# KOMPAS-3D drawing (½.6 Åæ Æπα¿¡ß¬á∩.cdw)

Views: Вид 1
Referenced files in C:\Program Files\ASCON\KOMPAS-3D V10\Sys\: SPDS.lcs, Graphic.lcs
Referenced files in \\F-server\проектирование\Проекты\РЗА и ПА Тюменские РС\4. Проект\ЭП\Туринская\Рабочая документация\: план располодения оборудования на ПС.cdw
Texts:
  Текст на чертеже
  Размерные надписи
  Шероховатость
  Линия-выноска #1
  Линия-выноска #2
  Линия-выноска #3
  Отклонения формы и база
  Заголовок таблицы
  Ячейка таблицы
  Стрелка вида
  Обозначение изменения
  Фигурная скобка
  Номер узла
  Марка координационной оси
  VRCB
  Выносная надпись
  Обозначение узла
  Марка/позиционное обозначение с линией-выноской
  Марка/позиционное обозначение на линии
  Марка/позиционное обозначение без линии-выноски
  Лит-Масса-Масштаб
  Материал-Предприятие
  Title Specification
  Body Specification ( left align )
  Body Specificaton ( centered )
  Без имени
  Normal
  heading 1
  Знак Знак Знак Знак Знак Знак
  Verdana
  Body Text
  MS Sans Serif
  Txt
  Simplex
  TXT
  Обычный
  Термин
  Список определений
  Адрес
  Цитаты
  Форматированный
  Courier New
  Z-конец формы
  Z-начало формы
  Additional DXF text style 0
  Абзац Знак
  Body Text 3
  Title
  ТекстШаг1
  Шрифт 2.5
  Заголовки
  txt
  heading 2
  AGOpus
  footer
  Денис
  RUSTXT
  Обычный (веб)
  ООббыыччнныыйй
  Definition Term
  Definition List
  Address
  Blockquote
  Preformatted
  z-Bottom of Form
  z-Top of Form
  header
  NormalParagraphStyle
  ссылки
  Подпись в квадратике
  табл
  цепи
  Маркировка
  клеммы, контакты
  тексты табл
  Тексты. 3,2
  ЗОНА_привяз
  текст переноса
  ТТееррммиинн
  ССппииссоокк ооппррееддееллеенниийй
  ААддрреесс
  ЦЦииттааттыы
  ФФооррммааттиирроовваанннныыйй
  Z-ккооннеецц ффооррммыы
  Z-ннааччааллоо ффооррммыы
  GOST 2.304 type A
  rustxt
  heading 8
  heading 3
  heading 6
  heading 7
  russ
  heading 4
  heading 5
  heading 9
  HeliosLight
  Pa3
  Pa1
  Три с половиной
  style2
  Table Contents
  Table Heading
  ГОСТ_МНЕ
  ESK - Обозначение
  маркировка
  ISOCP
  ROMANS
  SIMPLEX
  Текст 3,5
  Tahoma
  CNBNDG+TimesNewRoman
  Subtitle
  FR5
  romanc
  eskd1
  Pa15
  Pa18
  Аппараты
  подписи
  Состав чартежа
  ячейка табл.
  Ссылки
  Пояснения
  Клеммник текст
  CM12
  romans
  gif
  Пояснения 2
  текст табл
  ISOCPEUR
  CC С?т?и?л?ь? П?о? ц?е?н?т?р?у?
  Normal (Web)
  ошиновка
  Топосъемка
  лотки
  Демонтаж
  Монтаж
  Номер
  на плане
  Постоянные здания и сооружения
  ОПУ
  Существующее
  КРУН 10 кВ
  Трансформатор 1Т, маслоприемник
  Существующий
  Трансформатор 2Т, маслоприемник
  Временные здания и сооружения
  III
  Вагон-дом для кратковременного отдых рабочих
  Уборная
  Дизельная электростанция
  Контейнеры для ТБО (0,75м 3 )и жидких хоз.-быт.стоков(1м 3 )
  «Екатерина» 9,0х3,0
  Туалетная кабина "Люкс"
  ОАО ПКТИпромстрой
  АДС 45-Т400 РЯ
  Экспликация зданий и сооружений
  Примечания:
  1. Для нужд строительства (размещение задействованного в строительстве персонала, обеспечение электроэнергией)
  использовать временные мобильные инвентарные здания;
  2. При выполнении всех строительно-монтажных работ на площадке необходимо руководствоваться требованиями
  СНиП 12-03-2001 "Безопасность труда в строительстве. Общие требования", СНиП 12-04-2002 "Безопасность труда в
  строительстве. Строительное производство", а также ПОТ-РМ-016-2001/РД 153-34.0-03.150-00 "Межотраслевые правила по
  охране труда (правила безопасности) при эксплуатации электроустановок";
  3. Наружное освещение строительной площадки осуществляется за счет существующего освещения;
  4. Под временные сооружения (поз. II, III и IV) устраивается площадка из дорожных плит ПД 60-20 на щебеночном основании
  толщиной 15см;
  5. На период строительства для электроснабжения временных зданий и сооружений использовать дизельную электростанцию.
  Прокладку  кабеля от дизельной электростанции до вагончиков выполнить в воздушном исполнении в гофрированной трубе
  диаметром 30 мм, на вагончиках кабель закрепить скобами. Щиток временного электроснабжения навесить на стенку
  вагона-дома для отдыха рабочих;
  6. На паспорте-стенде строительного объекта  должен быть план пожарной защиты с нанесенными строящимися и
  вспомогательными зданиями и сооружениями, въездами, подъездами, местонахождениями водоисточников, средств пожаротушения
  и связи (согласно ППБ-01-03 п.575);
  7. Условные обозначения см. 16/01-ПОС,л.1.
  8. Тонкой линией изображено существующее оборудование, замена которого проектом не предусматривается,  утолщенной -
  демонтируемое оборудование.
  н.пр.64.19
  н.пр.67.98
  н.пр.66.93
  н.пр.63.61
  н.пр.63.65
  н.пр.63.18
  н.пр.64.50
  н.пр.64.34
  h.забора 57.97
  н.пр.64.73
  h.забора 57.91
  н.пр.60.52
  н.пр.60.25
  h.забора 57.82
  h.забора 58.00
  н.пр.66.71
  н.пр.59.26
  н.пр.59.52
  н.пр.59.49
  ЗРУ 10кВ
  каб. в землю
  н.пр.63.84
  тр-р
  кабель в землю
  б/пр.
  каб.лоток
  ВЛ 110кВ
  ВЛ 10кВ
  емк.для маслослива
  КМУ ИНМАН ИМ-150
  АГП-22
  K5LT_BASIC_RGB_0_0_255_THICK_0.6
  CONTI_RGB_168_0_168_THICK_0.13
  CONTI_RGB_168_80_0_THICK_0.13
  CONTI_RGB_0_0_0_THICK_0.13
  CONTI_RGB_0_0_0_THICK_0.3
  POLYLINE_STYLE_0.18_RGB_0_0_0
  K5LT_AXLED_RGB_255_128_0_SC_1_THICK_0.18
  Стили документа
  Бортовой автомобиль КамАЗ 43114-027-02
  АТ ППР#010#0104
  АГП
  Автогидроподъемник АГП-18-04
  АГП ППР#140#0102
  ГИП
  Н.контр.
  Гл.спец
  Провер.
  Разраб.
  Перезавод ВЛ на ПС Тюмень. Реконструкция устройств
  РЗ и ПА на обратных концах отходящих ВЛ,
  ВОЛС Тюменского ТПО
  Матвеев
  Ромин
  Шашерин
  Королева
  Микрюков
  ПС 110/10 кВ Туринская
  Строительный генеральный план
  Общие технические условия на средний ремонт
Dimensions and other numbers on the sheet: 16/01-ПОД; 7; 2,5; 1,8; 2.5; 3,2_; 3.5; 3,2; 2,5 (контакты, клеммы); 3,2 (надписи); 3,2 (Зоны); 5; 2,5_01; 2,5_3; 3,5_01; 3,5_tabl; 5_заголовок; 2,3_; 3,2_зона не привяз; 3,5; 3.2 маркировка; 3,2 элементы; 3,2 линия; 3,2 таблица; 2,5 грязносинь; 2.5 курсив; 2.5_Э5_надписи; 2.5_Э5_ссылки; 2.5_кабель; 3.2; 2.5 надписи; 3 и 5; 5,0_белый_подчёркнутый; 3.2 фиол; 3.2 (текст); 1; 2; 3; 4; 56; 58; 56.34; 56.82; 56.51; 56.04; 56.85; 56.28; 56.56; 58.19; 56.60; 56.03; 56.69; 56.23; 56.39; 56.41; 56.59; 56.48; 56.92; 56.66; 57.00; 56.75; 56.91; 56.49; 56.72; 58.61; 56.77; 56.26; 58.53; 56.45; 56.32; 56.90; 56.47; 56.44; 56.95; 56.02; 59.33; 57.36; 58.00; 56.31; 56.29; 58.49; 58.36; 56.79; 56.30; 56.35; 57.74; 56.63; 56.14; 55.97; 57.73; 58.12; 56.62; 58.03; 57.60; 57.94; 56.01; 57.19; 58.43; 58.33; 57.23; 57.34; 57.76; 56.33; 57.77; 57.72; 57.88; 58.23; 56.76; 56.09; 56.73; 57.81; 57.78; 57.24; 58.46; 56.65; 57.80; 58.47; 57.25; 57.39; 56.78; 56.17; 56.71; 56.64; 56.83; 57.05; 57.21; 57.13; 57.18; 56.11; 673250; 673300; 3пр.; 7пр.; 56.99; 56.96; 05.13; 6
